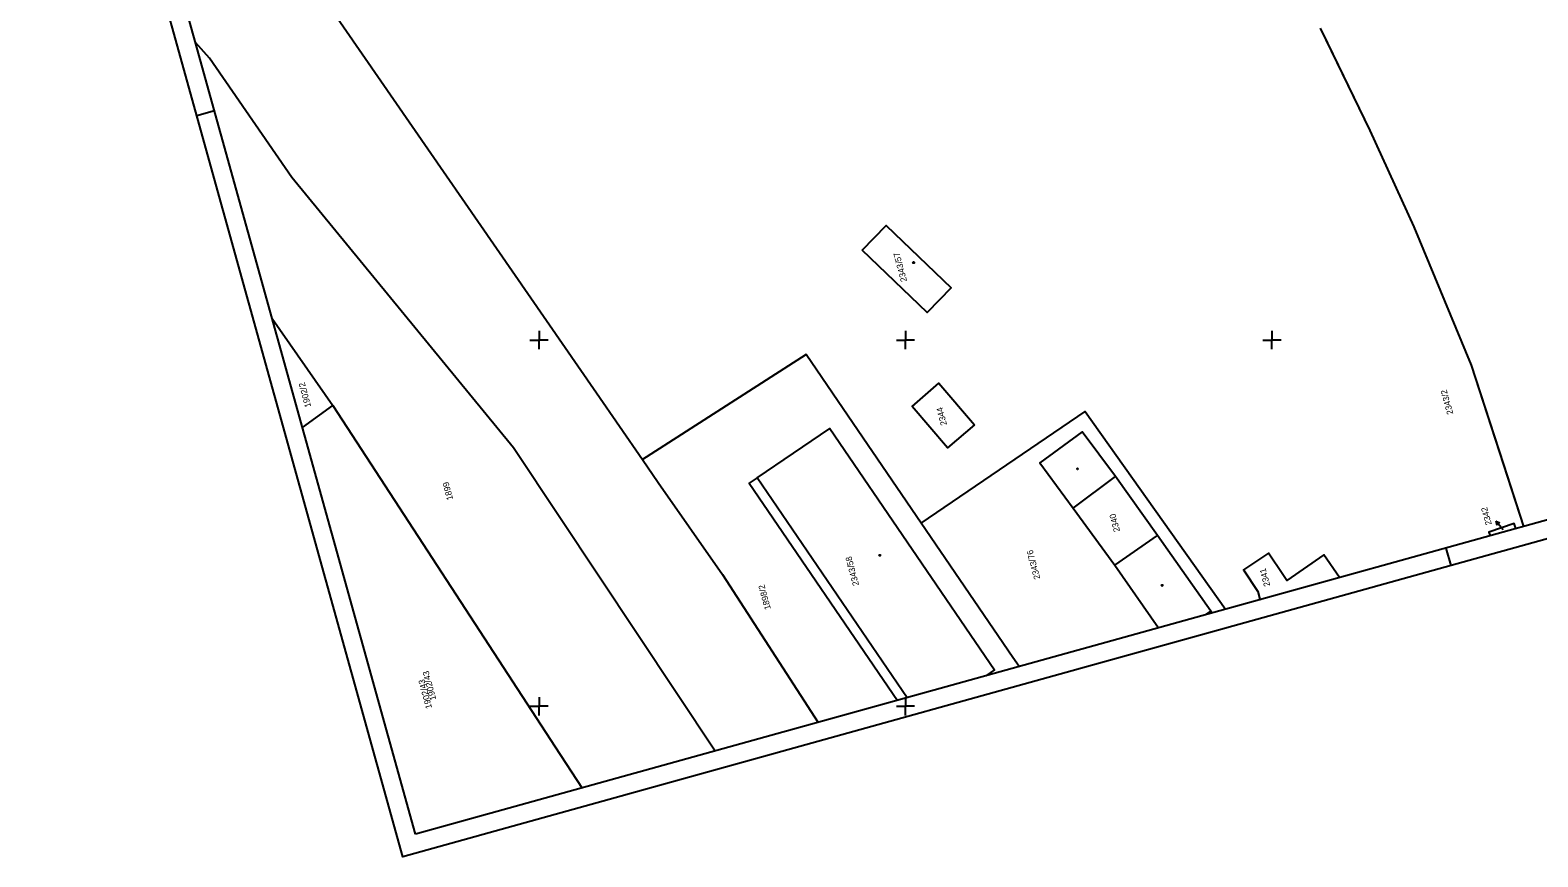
# Model space of a CAD drawing. Extents: x -821172 to -820632, y -1070921 to -1069931.
# Drawn here: x -820969.5 to -820763.7, y -1070920.6 to -1070807.7 of the extents above; entities that cross this region are included whole.
import ezdxf

# ---------------------------------------------------------------- set-up
doc = ezdxf.new("R2010")
doc.units = 0
for name, color, linetype in [('Ram', 7, 'Continuous'), ('Sit', 7, 'Continuous'), ('Vrstva 53', 7, 'Continuous'), ('Vrstva 55', 7, 'Continuous'), ('Vrstva 56', 7, 'Continuous'), ('Vrstva 57', 7, 'Continuous'), ('Vrstva 59', 7, 'Continuous')]:
    doc.layers.add(name, color=color, linetype=linetype)

msp = doc.modelspace()

# ---------------------------------------------------------------- linework, layer by layer
at = {"layer": 'Ram'}
for p, q in [((-820944.32, -1070818.73), (-820946.73, -1070819.4)), ((-820775.54, -1070880.81), (-820776.21, -1070878.4))]:
    msp.add_line(p, q, dxfattribs=at)
for points in [[(-820859.09, -1070034.8), (-820635.54, -1070839.32), (-820916.88, -1070917.49)], [(-820775.54, -1070880.81), (-820918.62, -1070920.57), (-821143.51, -1070111.23)], [(-820916.88, -1070917.49), (-821140.43, -1070112.97)], [(-820632.46, -1070841.06), (-820775.54, -1070880.81)]]:
    msp.add_lwpolyline(points, dxfattribs=at)
at = {"layer": 'Sit'}
for p, q in [((-820901.25, -1070850), (-820900, -1070850)), ((-820900, -1070848.75), (-820900, -1070850)), ((-820898.75, -1070850), (-820900, -1070850)), ((-820900, -1070851.25), (-820900, -1070850)), ((-820851.25, -1070850), (-820850, -1070850)), ((-820850, -1070848.75), (-820850, -1070850)), ((-820848.75, -1070850), (-820850, -1070850)), ((-820850, -1070851.25), (-820850, -1070850)), ((-820801.25, -1070850), (-820800, -1070850)), ((-820800, -1070848.75), (-820800, -1070850)), ((-820798.75, -1070850), (-820800, -1070850)), ((-820800, -1070851.25), (-820800, -1070850)), ((-820900, -1070898.75), (-820900, -1070900)), ((-820850, -1070898.75), (-820850, -1070900)), ((-820901.25, -1070900), (-820900, -1070900)), ((-820898.75, -1070900), (-820900, -1070900)), ((-820900, -1070901.25), (-820900, -1070900)), ((-820851.25, -1070900), (-820850, -1070900)), ((-820848.75, -1070900), (-820850, -1070900)), ((-820850, -1070901.25), (-820850, -1070900))]:
    msp.add_line(p, q, dxfattribs=at)
at = {"layer": 'Vrstva 53'}
msp.add_lwpolyline([(-820765.63, -1070875.45), (-820768.36, -1070867.01), (-820772.76, -1070853.45), (-820780.56, -1070834.55), (-820786.59, -1070821.38), (-820793.34, -1070807.43)], dxfattribs=at)
at = {"layer": 'Vrstva 55'}
msp.add_line((-820936.45, -1070847.05), (-820928.15, -1070858.94), dxfattribs=at)
for points in [[(-820957.35, -1070771.85), (-820930.99, -1070801.01), (-820892.18, -1070857.22), (-820885.9, -1070866.32)], [(-820765.63, -1070875.45), (-820772.76, -1070853.45), (-820780.56, -1070834.55), (-820786.59, -1070821.38), (-820793.08, -1070807.95)], [(-820875.97, -1070906.12), (-820897.16, -1070874.24), (-820903.48, -1070864.73), (-820933.76, -1070827.81), (-820944.98, -1070811.53), (-820946.92, -1070809.39)], [(-820855.92, -1070837.73), (-820852.62, -1070834.37), (-820843.79, -1070842.89), (-820847.05, -1070846.25), (-820855.92, -1070837.73)], [(-820847.86, -1070875.03), (-820857.84, -1070860.4), (-820863.58, -1070851.99), (-820885.4, -1070866), (-820885.9, -1070866.32)], [(-820840.58, -1070861.56), (-820844.26, -1070864.73), (-820849.11, -1070859.07), (-820845.46, -1070855.9), (-820840.58, -1070861.56)], [(-820932.32, -1070861.93), (-820928.15, -1070858.94)], [(-820928.15, -1070858.94), (-820897.82, -1070905.55), (-820894.12, -1070911.17)], [(-820847.86, -1070875.03), (-820825.47, -1070859.75), (-820806.33, -1070886.77)], [(-820870.26, -1070868.82), (-820860.32, -1070862.08), (-820837.84, -1070895.04), (-820839.05, -1070895.86)], [(-820808.16, -1070887.28), (-820808.34, -1070887.03), (-820815.61, -1070876.67), (-820821.34, -1070868.62), (-820825.9, -1070862.55), (-820831.68, -1070866.78), (-820827.12, -1070872.98), (-820821.43, -1070880.72), (-820815.46, -1070889.31)], [(-820885.9, -1070866.32), (-820883.74, -1070869.45), (-820874.96, -1070882.02), (-820861.9, -1070902.22)], [(-820849.77, -1070898.84), (-820870.26, -1070868.82)], [(-820834.51, -1070894.6), (-820835.36, -1070893.35), (-820847.86, -1070875.03)], [(-820766.68, -1070875.74), (-820766.91, -1070875.07), (-820770.38, -1070876.25), (-820770.22, -1070876.72)], [(-820790.75, -1070882.44), (-820792.92, -1070879.32), (-820797.95, -1070882.82), (-820798.5, -1070882), (-820800.44, -1070879.1), (-820803.88, -1070881.39), (-820801.91, -1070884.35), (-820801.62, -1070885.37), (-820801.56, -1070885.45)]]:
    msp.add_lwpolyline(points, dxfattribs=at)
at = {"layer": 'Vrstva 56'}
for p, q in [((-820827.12, -1070872.98), (-820821.34, -1070868.62)), ((-820821.43, -1070880.72), (-820815.61, -1070876.67)), ((-820809.07, -1070887.53), (-820808.34, -1070887.03))]:
    msp.add_line(p, q, dxfattribs=at)
msp.add_lwpolyline([(-820870.26, -1070868.82), (-820871.35, -1070869.56), (-820851.11, -1070899.22)], dxfattribs=at)
at = {"layer": 'Vrstva 57'}
for p, q in [((-820768.44, -1070875.9), (-820769.41, -1070874.75)), ((-820769.41, -1070874.75), (-820768.9, -1070874.97)), ((-820769.41, -1070874.75), (-820769.28, -1070875.3))]:
    msp.add_line(p, q, dxfattribs=at)
at = {"layer": 'Vrstva 59'}
for centre in [(-820848.9, -1070839.43), (-820826.52, -1070867.59), (-820853.51, -1070879.4), (-820814.97, -1070883.5)]:
    msp.add_circle(centre, 0.0875, dxfattribs=at)

# ---------------------------------------------------------------- texts
at = {"layer": 'Vrstva 57'}
for s, rotation, p in [('2343/57', 105, (-820849.78, -1070841.94)), ('1902/2', 105, (-820931.11, -1070859.08)), ('2343/2', 105.5289, (-820775.23, -1070860.05)), ('2344', 105, (-820844.33, -1070861.55)), ('1899', 105, (-820911.73, -1070871.74)), ('2342', 105.5289, (-820769.97, -1070875.16)), ('2340', 105, (-820820.71, -1070876.08)), ('2343/76', 105, (-820831.6, -1070882.56)), ('2343/58', 105, (-820856.33, -1070883.44)), ('2341', 105, (-820800.22, -1070883.53)), ('1898/2', 105, (-820868.37, -1070886.69)), ('1902/43', 105, (-820914.04, -1070899.07)), ('1902/43', 105, (-820914.61, -1070900.22))]:
    msp.add_text(s, height=0.85, rotation=rotation, dxfattribs=at).set_placement(p)

doc.saveas('drawing.dxf')
